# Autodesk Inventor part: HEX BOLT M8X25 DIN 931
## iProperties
Created: 2006-02
Part Number: HEX BOLT M8X25 DIN 931
Material: Steel, Mild
Description: Hex-Head Bolt
Document SubType Name: Modeling
Standard: DIN 931-1
Designer: Andy Moles
Standards Organization: DIN
Language: en-US
Size Designation: M8 x 35
Categories: <MemberInstance><Categories><Category DisplayName="Fasteners" InternalName="e4da775c-781d-43d5-af7c-5136215cf5a6" Mnemonic="FSTN"><Category DisplayName="Bolts"
Density: 1 g/cm^3
Author: Andy Moles
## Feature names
1. Body [Revolution]
2. Head [Extrusion]
3. Chamfer1 [Revolution]
4. Chamfer2
